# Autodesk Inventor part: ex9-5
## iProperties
Created: 2006-03
Part Number: ex9-5
Document SubType Name: Sheet Metal
Designer: Elise Moss
Author: Elise Moss
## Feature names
1. Plate1
2. Bend1
3. Plate2
4. Bend2
5. Cut1
